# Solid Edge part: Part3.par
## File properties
Author: Deepak Maini
Template: Normal.par
Last saved by: Robert a Rhodes jr
Revision: 3
Application: Solid Edge
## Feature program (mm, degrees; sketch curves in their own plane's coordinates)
body "unnamed Body 1"
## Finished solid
Body 1: solid body, 59 faces, 124 edges, 64 vertices.
  Faces by surface: plane 29, cylinder 25, cone 5
  Edges by curve: circle 60, line 54, intersection 10
Bounding box of the edges (mm): 1353.852 x 457.200 x 1295.400, from (-676.9261, -203.2, -533.4) to (676.9261, 254, 762).
Cylindrical faces by radius (mm): R50.8 x3, R95.25 x3, R127 x4, R152.4 x5, R254 x1, R431.8 x5, R508 x1, R533.4 x3
Conical faces (half-angle, radius in mm at the cone's reference point): 47.7263 deg R292.1 x5
Planar faces by outward normal: +x 1, +y 11, +z 1, -x 1, -y 2, -z 1, oblique 12
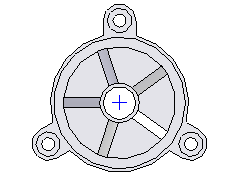
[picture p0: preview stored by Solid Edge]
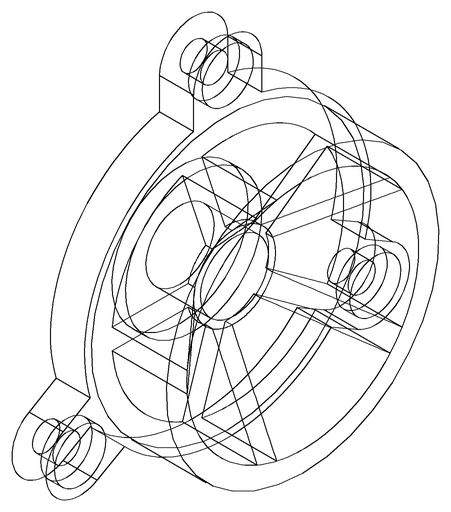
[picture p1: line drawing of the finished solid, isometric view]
